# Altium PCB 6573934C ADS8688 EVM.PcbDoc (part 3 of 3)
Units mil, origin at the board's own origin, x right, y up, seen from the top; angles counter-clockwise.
Board outline 4100 x 2700 mil, 6 copper layers (L1_Analog, L2_GND, L3_AnalogPower, L4_DigPower, L5_GND, L6_Digital), stack 58.4 mil thick; 282 components, 187 nets, 719 pads, 318 vias.
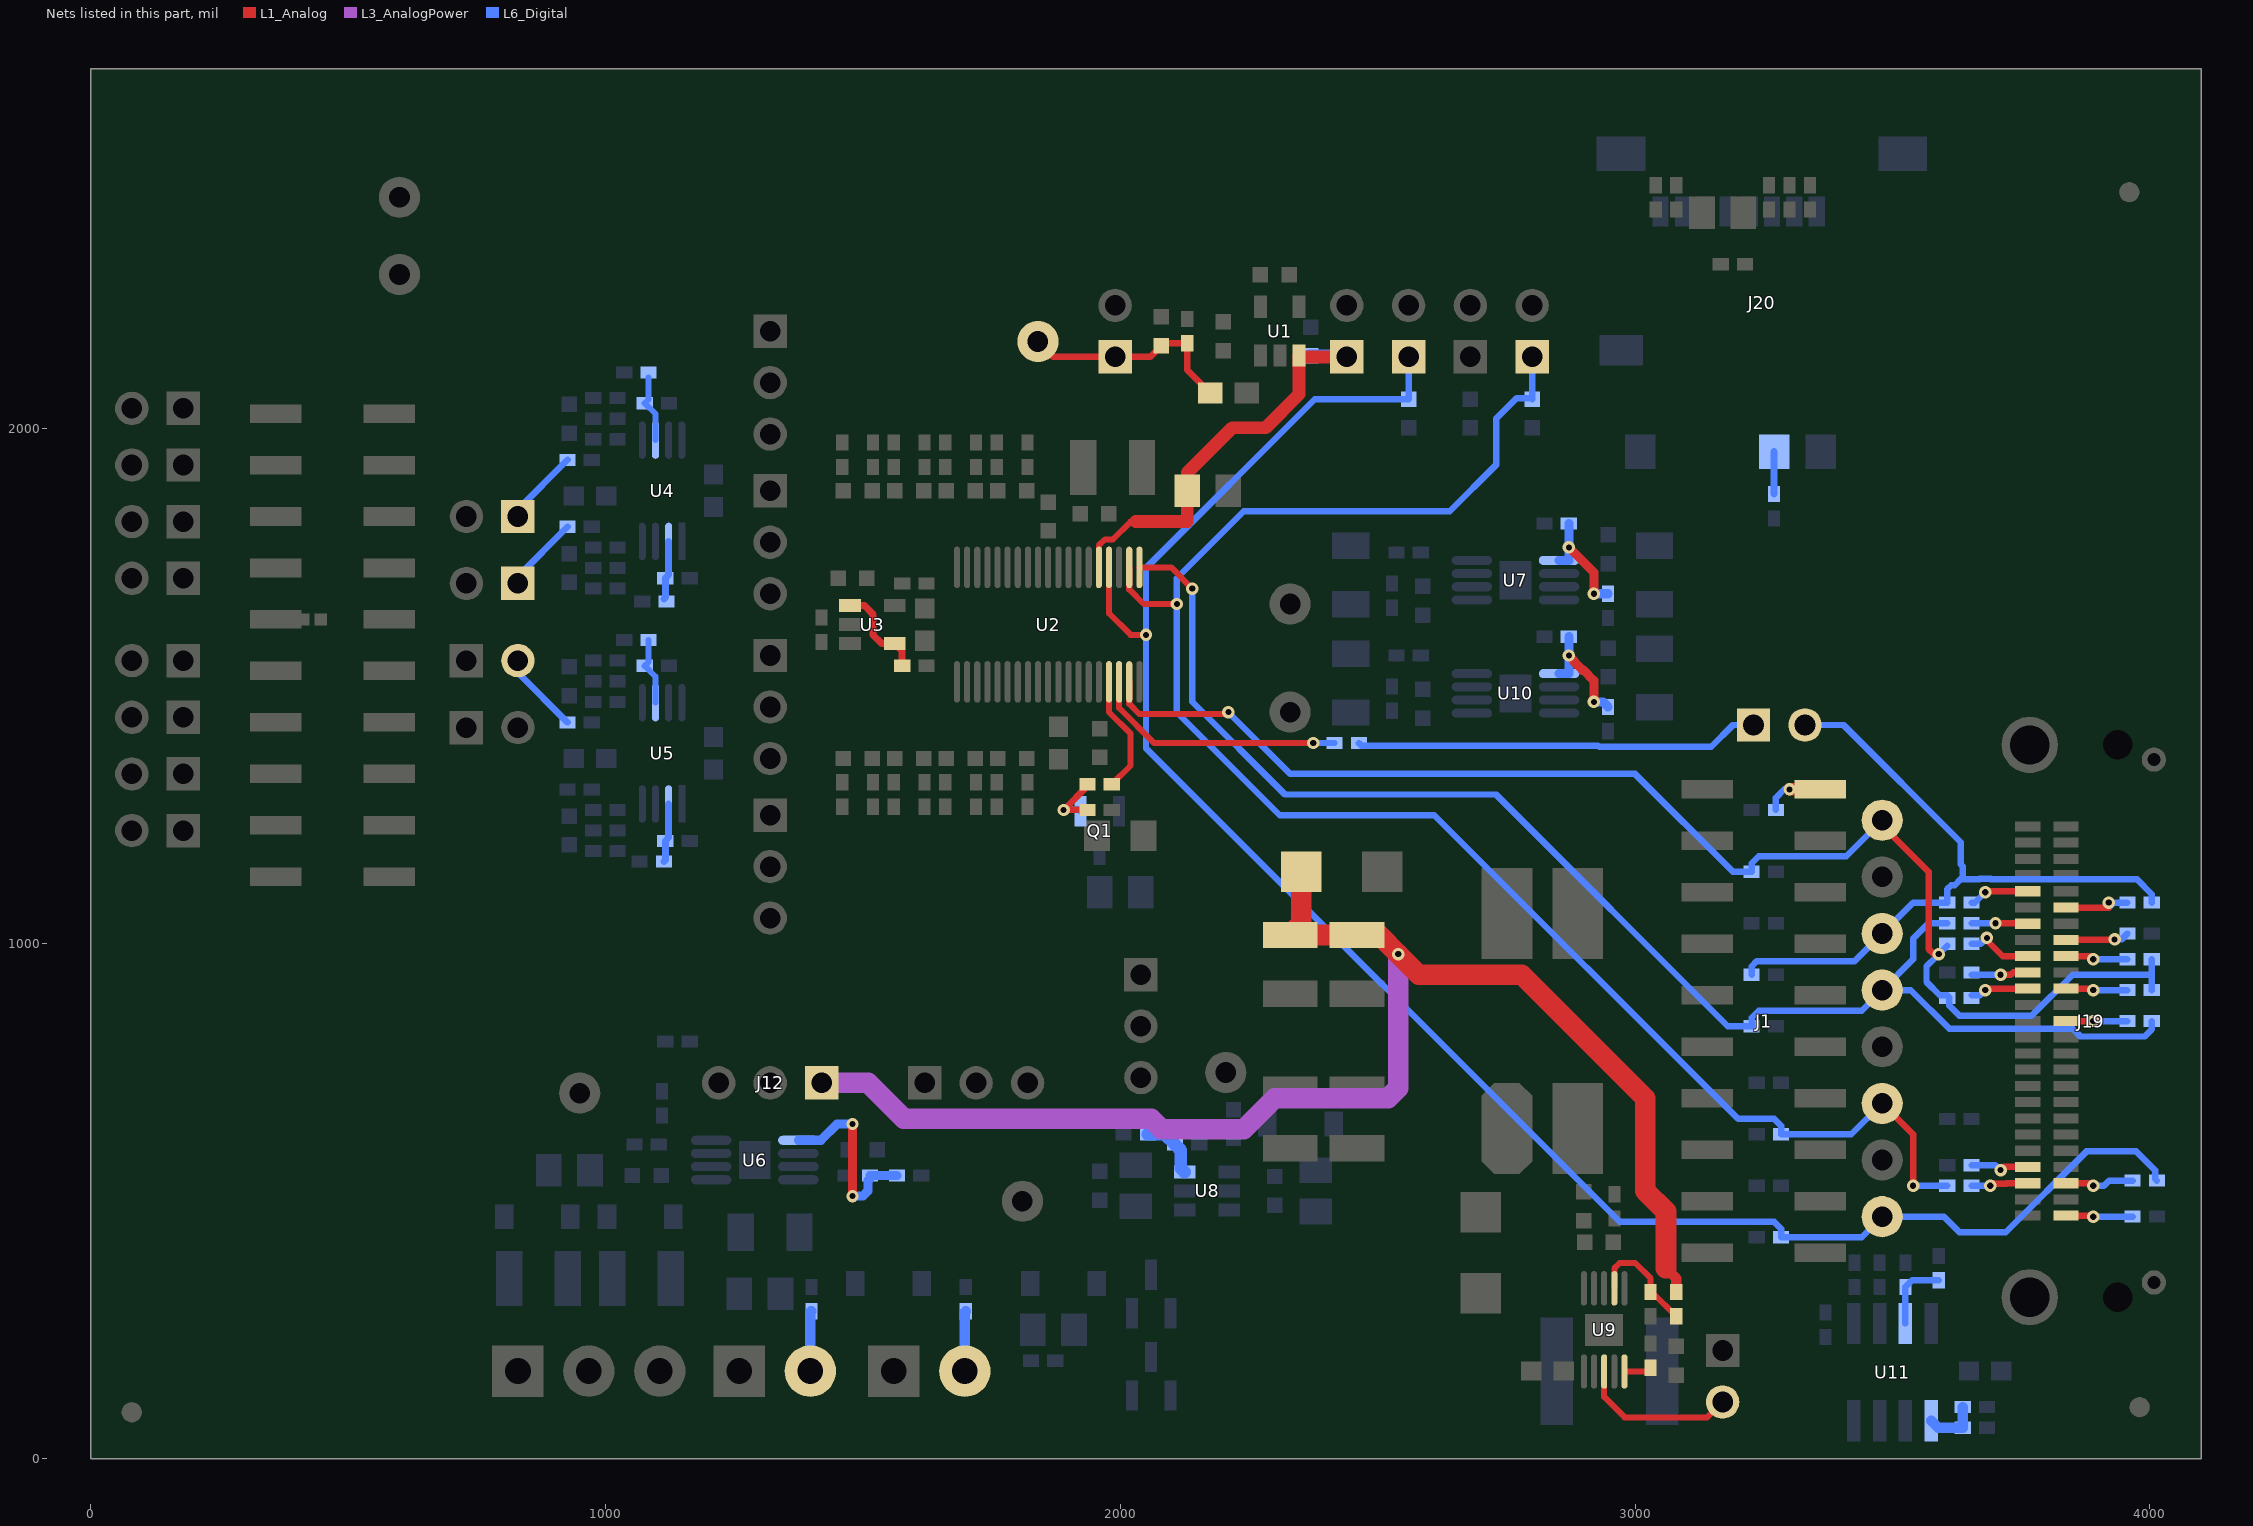
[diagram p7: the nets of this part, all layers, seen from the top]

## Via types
v1: diameter 24, hole 12, L1_Analog to L6_Digital, tented both sides, 318 vias

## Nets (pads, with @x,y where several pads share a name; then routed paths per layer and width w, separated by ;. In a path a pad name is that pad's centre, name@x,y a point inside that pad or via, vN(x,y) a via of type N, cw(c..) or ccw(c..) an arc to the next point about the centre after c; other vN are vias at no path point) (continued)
NetJ17_2: J17.2 U9.3 | length 308.3
  L1_Analog w11.81: U9.3@2940,169.29 2940,120 2980,80 3140,80 J17.2@3170,110
NetJ19_1: J19.1 R89.2 | length 130.2
  L1_Analog w12.52: J19.1@3837.01,472.05 3887.95,472.05 v1(3890,470)
  L6_Digital w12.52: v1(3890,470) R89.2@3966.38,470
NetJ19_5: J19.5 R91.2 | length 135.6
  L1_Analog w12.52: J19.5@3837.01,535.04 3884.96,535.04 v1(3890,530)
  L6_Digital w12.52: v1(3890,530) 3910.71,530 3920.71,540 R91.2@3966.38,540
NetJ19_6: J19.6 R87.1 | length 112.4
  L1_Analog w12.52: v1(3690,530) 3695.04,535.04 3698,535.04 3699.17,533.87 3720.83,533.87 3722,535.04 J19.6@3762.99,535.04
  L6_Digital w12.52: R87.1@3653.62,530 v1(3690,530)
NetJ19_8: J19.8 R86.1 | length 117.2
  L1_Analog w12.52: v1(3710,560.5) 3710,560 3716.54,566.54 J19.8@3762.99,566.54
  L6_Digital w12.52: R86.1@3653.62,570 3700,570 3710,560 v1(3710,560.5)
NetJ19_25: J19.25 R100.2 | length 119.4
  L1_Analog w12.52: J19.25@3837.01,850 v1(3890,850)
  L6_Digital w12.52: v1(3890,850) R100.2@3956.38,850
NetJ19_29: J19.29 R99.2 | length 120.6
  L1_Analog w12.52: J19.29@3837.01,912.99 3887.01,912.99 v1(3890,910)
  L6_Digital w12.52: v1(3890,910) R99.2@3956.38,910
NetJ19_30: J19.30 R107.1 | length 131.1
  L1_Analog w12.52: v1(3680,910) 3682.99,912.99 J19.30@3762.99,912.99
  L6_Digital w12.52: v1(3680,910) 3670,900 ; 3670,900 3653.62,900 3670,900
NetJ19_32: J19.32 R103.1 | length 111.2
  L1_Analog w12.52: v1(3710,940) 3730,940 3734.49,944.49 J19.32@3762.99,944.49
  L6_Digital w12.52: R103.1@3653.62,940 v1(3710,940)
NetJ19_33: J19.33 R93.2 | length 121.8
  L1_Analog w12.52: J19.33@3837.01,975.98 3884.02,975.98 v1(3890,970)
  L6_Digital w12.52: v1(3890,970) R93.2@3956.38,970
NetJ19_34: J19.34 R101.1 | length 150
  L1_Analog w12.52: v1(3683.36,1011.56) 3683.36,1006.64 3714.02,975.98 J19.34@3762.99,975.98
  L6_Digital w12.52: v1(3683.36,1011.56) 3671.81,1000 ; 3671.81,1000 R101.1@3653.62,1000 3671.81,1000
NetJ19_35: J19.35 R90.2 | length 124.6
  L1_Analog w12.52: J19.35@3837.01,1007.48 3930.4,1007.48 v1(3931.46,1008.54)
  L6_Digital w12.52: v1(3931.46,1008.54) 3944.92,1008.54 R90.2@3956.38,1020
NetJ19_38: J19.38 R88.1 | length 109.8
  L1_Analog w12.52: v1(3700,1040) 3761.97,1040 J19.38@3762.99,1038.98
  L6_Digital w12.52: R88.1@3653.62,1040 v1(3700,1040)
NetJ19_39: J19.39 R92.2 | length 143.7
  L1_Analog w12.52: J19.39@3837.01,1070.47 3919.53,1070.47 3920,1070 v1(3920,1080)
  L6_Digital w12.52: v1(3920,1080) 3920,1070 3930,1080 R92.2@3956.38,1080
NetJ19_42: J19.42 R98.1 | length 118.5
  L1_Analog w12.52: v1(3680,1100) 3681.97,1101.97 J19.42@3762.99,1101.97
  L6_Digital w12.52: R98.1@3653.62,1080 3660,1080 v1(3680,1100)
NetJ20_9: J20.9 R85.1 | length 82.2
  L6_Digital w13.78: R85.1@3270,1873.62 J20.9@3270,1955.83
NetJ21_1: J21.1 R16.2 | length 786.8
  L6_Digital w12.52: R16.2@2463.62,1390 2468.62,1385 2927.92,1385 2930.05,1382.87 3147.87,1382.87 3190,1425 J21.1@3230,1425
NetJ25_1: J25.1 R46.2 | length 149.9
  L6_Digital w12.52: J25.1@830,1830 830,1843.62 R46.2@926.38,1940
NetJ30_2: J30.2 R54.2 | length 159.9
  L6_Digital w12.52: J30.2@830,1550 830,1526.38 R54.2@926.38,1430
NetJ31_1: J31.1 R42.1 | length 149.9
  L6_Digital w12.52: J31.1@830,1700 830,1713.62 R42.1@926.38,1810
NetJ32_2: J32.2 R69.1 | length 117.2
  L6_Digital w20: J32.2@1398,170 1398,284.38 R69.1@1400,286.38
NetJ33_2: J33.2 R106.1 | length 117.2
  L6_Digital w20: J33.2@1698,170 1698,284.38 R106.1@1700,286.38
NetQ1_1: Q1.1 R17.1 R20.2 | length 149.3
  L1_Analog w12.52: R20.2@1936.38,1260 v1(1890,1260) 1936.38,1306.38 R17.1@1936.38,1310
  L6_Digital w12.52: v1(1890,1260) 1920,1260 Q1.1@1922.6,1257.4
NetR10_1: R10.1 U3.1 U3.4 | length 190
  L1_Analog w13.78: U3.1@1475,1657 1503,1657 1520,1640 1520,1600 1537,1583 U3.4@1562,1583 1576.38,1568.62 R10.1@1576.38,1540
NetR16_1: R16.1 U2.36 | length 497.5
  L1_Analog w11.81: U2.36@1997.8,1508.78 1997.8,1458.02 2065.82,1390 v1(2375,1390)
  L6_Digital w11.81: v1(2375,1390) R16.1@2416.38,1390
NetR17_2: R17.2 U2.35 | length 231.2
  L1_Analog w11.81: U2.35@1978.11,1508.78 1978.11,1451.89 1978.11,1449.87 2020,1407.98 2020,1346.38 R17.2@1983.62,1310
NetR33_1: R33.1 R36.2 U4.2 | length 115.4
  L6_Digital w13.78: R36.2@1113.62,1670 1116.38,1672.76 R33.1@1116.38,1710 1122.8,1716.42 U4.2@1122.8,1781.57
NetR39_1: R39.1 R44.2 U4.6 | length 133.2
  L6_Digital w11.81: R44.2@1083.62,2100 1083.62,2057.24 R39.1@1076.38,2050 1097.2,2029.17 U4.6@1097.2,1978.43
NetR47_1: R47.1 R48.1 U5.2 | length 115.4
  L6_Digital w13.78: R48.1@1113.62,1160 1116.38,1162.76 R47.1@1116.38,1200 1122.8,1206.42 U5.2@1122.8,1271.57
NetR49_1: R49.1 R52.1 U5.6 | length 133.2
  L6_Digital w11.81: R52.1@1083.62,1590 1083.62,1547.24 R49.1@1076.38,1540 1097.2,1519.17 U5.6@1097.2,1468.43
NetR58_1: R58.1 R62.1 U6.5 | length 376.8
  L1_Analog w17.72: v1(1480,510) v1(1480,650)
  L6_Digital w17.72: U6.5@1374.65,618.39 1418.39,618.39 1450,650 v1(1480,650) ; v1(1480,510) 1500,510 1510,520 1510,540 1513.62,543.62 R58.1@1513.62,550 R62.1@1566.38,550
NetR60_1: R60.1 R64.2 U7.5 | length 228.5
  L1_Analog w17.72: v1(2871.34,1770) 2920,1721.34 v1(2920,1680)
  L6_Digital w17.72: U7.5@2852.36,1744.76 2871.34,1744.76 v1(2871.34,1770) R64.2@2871.34,1816.38 ; v1(2920,1680) R60.1@2947.72,1680
NetR63_2: R63.2 R65.1 U8.3 | length 121.8
  L6_Digital w25: R65.1@2053.62,630 2086.38,630 R63.2@2106.38,610 2117.5,598.88 2117.5,564.5 U8.3@2125,557
NetR66_2: R66.2 R67.1 U9.7 | length 221.9
  L1_Analog w11.81: U9.7@2959.69,330.71 2959.68,369.68 2970,380 3000,380 3030,350 R66.2@3030,323.62 3032.75,323.62 R67.1@3080,276.38
NetR68_2: R68.2 U9.5 | length 53.6
  L1_Analog w11.81: U9.5@2979.37,169.29 3022.91,169.29 R68.2@3030,176.38
NetR72_1: R72.1 R75.2 U10.5 | length 233.8
  L1_Analog w17.72: v1(2871.34,1560) 2881.27,1550.07 2881.27,1548.1 2898.1,1531.27 2900.07,1531.27 2920,1511.34 v1(2920,1470)
  L6_Digital w17.72: U10.5@2852.36,1524.76 2871.34,1524.76 v1(2871.34,1560) R75.2@2871.34,1596.38 ; v1(2920,1470) 2937.72,1470 R72.1@2947.72,1460
NetR96_2: R96.2 R104.1 U11.7 | length 181.3
  L6_Digital w12.52: U11.7@3525,262.5 R96.2@3525,333.38 3538,346.38 3550,346.38 ; 3550,346.38 R104.1@3590,346.38 3550,346.38
NetR97_1: R97.1 R102.2 U11.1 | length 107
  L6_Digital w20: U11.1@3575,73.5 3588.5,60 R97.1@3636.38,60 R102.2@3636.38,100
P18V: C32.1 C35.1 D2.1 J12.1 R67.2 | length 2804.7
  L1_Analog w20: 3060,370 3080,350 R67.2@3080,323.62
  L1_Analog w40: D2.1@2351.26,1140 2351.26,1038.35 C35.1@2330,1017.09 C32.1@2460,1017.09 2502.91,1017.09 v1(2540,980) 2580,940 2780,940 3020,700 3020,520 3060,480 3060,370
  L3_AnalogPower w40: J12.1@1420,730 1510,730 1580,660 2060,660 2080,640 2240,640 2300,700 2520,700 2540,720 v1(2540,980)
R\E\F\S\E\L\: J2.1 R9.1 R18.2 R91.1 TP9.1 U2.4 | length 3750.2
  L1_Analog w11.81: U2.4@1978.11,1731.22 1978.11,1641.89 2020,1600 v1(2050,1600)
  L6_Digital w12.52: J2.1@2560,2140 R18.2@2560,2058 2378,2058 2050,1730 v1(2050,1600) 2050,1380 2970,460 3270,460 3283.62,446.38 R9.1@3283.62,430 3440,430 TP9.1@3480,470 3600,470 3630,440 3720,440 3876.64,596.64 3973.36,596.64 4010,560 4010,543.42 4013.42,540 R91.1@4013.62,540
R\S\T\/P\D\: J3.1 R3.1 R13.2 R87.2 TP2.1 U2.2 | length 3372.8
  L1_Analog w11.81: U2.2@2017.48,1731.22 2017.48,1688.62 2046.1,1660 v1(2110,1660)
  L1_Analog w12.52: TP2.1@3480,690 3540,630 v1(3540,530)
  L6_Digital w12.52: J3.1@2800,2140 R13.2@2800,2058 2798,2060 2770,2060 2730,2020 2730,1930 2640,1840 2240,1840 2110,1710 v1(2110,1660) 2110,1450 2310,1250 2610,1250 3200,660 3270,660 3283.62,646.38 R3.1@3283.62,630 3420,630 TP2.1@3480,690 ; v1(3540,530) R87.2@3606.38,530
REFIN: C3.1 C7.1 J5.1 U1.3 U2.5 | length 848.8
  L1_Analog w11.81: U2.5@1958.43,1731.22 1958.43,1773.82 1969.96,1785.35 1985.35,1785.35 2020,1820 2030,1820
  L1_Analog w25: 2030,1820 2130,1820 C7.1@2130,1880 2130,1915 2217.5,2002.5 2282.5,2002.5 2347.4,2067.4 U1.3@2347.4,2142.76 2350.16,2140 J5.1@2440,2140
  L6_Digital w25: C3.1@2370,2142 2438,2142 J5.1@2440,2140
REFOUT: C6.1 J6.1 R1.2 R19.1 TP10.1 | length 428.2
  L1_Analog w12.52: TP10.1@1840,2170 1870,2140 J6.1@1990,2140 2058,2140 C6.1@2080,2162 2084.38,2166.38 R1.2@2130,2166.38 2130,2114.57 R19.1@2174.57,2070
SCLK: R6.1 R93.1 R99.1 R101.2 R107.2 TP6.1 U2.37 | length 2655.5
  L1_Analog w11.81: U2.37@2017.48,1508.78 2017.48,1466.18 2037.4,1446.26 2206.26,1446.26 v1(2210,1450)
  L1_Analog w12.52: TP6.1@3480,1240 3480,1230 3570,1140 3570,990 3580,980 v1(3590,980)
  L6_Digital w12.52: v1(2210,1450) 2330,1330 3000,1330 3190,1140 R6.1@3226.38,1140 3226.38,1156.38 3240,1170 3410,1170 TP6.1@3480,1240 ; R107.2@3606.38,900 3592,900 3566,926 3566,956.17 3584.78,974.94 3584.95,974.94 R101.2@3606.38,996.37 ; R107.2@3610,896.38 3610,880 3630,860 3770,860 3850,940 4003.62,940 ; R99.1@4003.62,910 4003.62,940 ; R93.1@4003.62,970 4003.62,940
SDI: R5.1 R88.2 R100.1 TP5.1 U2.1 | length 2766
  L1_Analog w11.81: U2.1@2037.17,1731.22 2098.78,1731.22 v1(2140,1690)
  L6_Digital w12.52: v1(2140,1690) 2140,1470 2320,1290 2730,1290 3180,840 R5.1@3226.38,840 3226.38,856.38 3240,870 3440,870 TP5.1@3480,910 ; R88.2@3606.38,1040 3570,1040 3540,1010 3540,970 TP5.1@3480,910 ; R100.1@4003.62,850 4003.62,833.62 3990,820 3865,820 3850,835 3610.55,835 3535.55,910 TP5.1@3480,910
SDO: J21.2 R4.1 R92.1 R98.2 TP4.1 | length 1379.8
  L6_Digital w12.52: R4.1@3226.38,940 3226.38,956.38 3235.95,965.95 3395,965.95 3425.24,965.94 3425.59,965.59 TP4.1@3480,1020 3540,1080 R98.2@3606.38,1080 3606.38,1106.38 3613.87,1113.87 3620.83,1113.87 3632.74,1125.78 ; J21.2@3330,1425 3405,1425 3632.74,1197.26 3632.74,1154.22 3636.13,1150.82 3636.13,1129.18 3632.74,1125.78 ; R92.1@4003.62,1080 4003.62,1096.38 3974.22,1125.78 3691.18,1125.78 3690.83,1126.13 3669.17,1126.13 3668.82,1125.78 3632.74,1125.78
VBUS_LP: J1.2 R61.2 | length 116.8
  L1_Analog w24: v1(3300,1300) J1.2@3360,1300
  L6_Digital w12.52: R61.2@3273.62,1260 3273.62,1283.62 3290,1300 v1(3300,1300)
pads on no net: D9.1 FID1.1 FID2.1 FID3.1 FID4.1 FID5.1 FID6.1 H1.0 H2.0 H3.0 H4.0 J19.M1 J19.M2 J19.MH1 J19.MH2 J19.MH3 J19.MH4 SH-J2.0 SH-J3.0 SH-J4.0 SH-J5.0 SH-J6.0 SH-J8.0 SH-J9.0 SH-J10.0 SH-J11.0 SH-J12.0 SH-J13.0 SH-J14.0 SH-J15.0 SH-J16.0 SH-J17.0 SH-J21.0 SH-J22.0 SH-J23.0 SH-J24.0 SH-J25.0 SH-J26.0 SH-J27.0 SH-J28.0 SH-J29.0 SH-J30.0 SH-J31.0 U6.3 U6.7 U7.3 U7.7 U9.6 U10.3 U10.7

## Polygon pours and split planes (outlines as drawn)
GND on L6_Digital "L6_Digital-No Net" (solid, remove dead copper, pour order 34): 0,0 0,2700 4105,2700 4105,0
DVDD on L4_DigPower "L4_DigPower-No Net" (solid, remove dead copper, pour order 23): 0,0 0,2700 4105,2700 4105,0
NetD2_2 on L1_Analog "Top Layer-No Net 4" (solid, pour order 24): 2320,1190 2470,1190 2470,850 2320,850 2320,1180
P18V on L1_Analog "Top Layer-No Net 3" (solid, pour order 22): 2000,960 2000,1190 2320,1190 2320,960 2000,960
N18V on L1_Analog "Top Layer-No Net 1" (solid, pour order 18): 2000,660 2320,660 2320,400 2500,400 2500,290 2750,290 2750,200 2580,200 2580,190 2000,190 2000,660
GND on L1_Analog "Top Layer-No Net" (solid, pour order 21): 2320,660 1960,660 1960,870 1960,960 2320,960 2320,850 2470,850 2470,1060 2640,1060 2770,1060 2770,540 2590,540 2470,540 2470,730 2320,730 2320,660
NetC45_1 on L1_Analog "L1_Analog-No Net 1" (solid, remove dead copper, pour order 19): 2500,290 2499.87,290.13 2499.87,399.87 2320.13,399.87 2320,400 2320,690 2520,690 2520,540 2700,540 2700,730 2820,730 2830,720 2830,540 2830,470 2830,460 2910,380 2910,290 2500,290
GND on L1_Analog "L1_Analog-No Net" (solid, remove dead copper, pour order 33): 0,0 0,2700 4105,2700 4105,0
NetD10_2 on L3_AnalogPower "L3_AnalogPower-No Net 1" (solid, remove dead copper, pour order 25): 3010,1340 3010,230 3330,230 3340,240 3300,280 3300,1340
3V3_LP on L3_AnalogPower "L3_AnalogPower-No Net 2" (solid, remove dead copper, pour order 26): 3010,1350 2850,1350 2760,1260 2770,1250 2770,420 2770,382.59 2910.35,242.24 2918.38,250.27 3010,250.27
P18V on L3_AnalogPower "L3_AnalogPower-No Net 3" (solid, remove dead copper, pour order 27): 1960,600 1631.22,600 1630.53,600.68 1640,610.15 1640,980 1640,983.85 1730,1073.85 1736.15,1080 1970,1080
HVDD on L3_AnalogPower "L3_AnalogPower-No Net 4" (solid, remove dead copper, pour order 28): 1970,1090 1970,870 2190,1090 1970,1090
HVSS on L3_AnalogPower "L3_AnalogPower-No Net 5" (solid, remove dead copper, pour order 29): 2030,1450 2640,1450 2350,1160 2340,1160 1760,1160 1750,1150 1740,1150 1670,1150 1660,1140 1560,1040 1270,1040 1250,1020 1240,1010 1200,1010 1070,880 680,880 680,1070 690,1060 1130,1060 1173.24,1060 1298.75,1185.51 1301.35,1188.11 1477.66,1188.11 1493.32,1188.11 1569.43,1264.22 1583.65,1250 1950,1250 1950,1450 1947.75,1452.25 1947.75,1481.28 1951.28,1481.28 1990,1520 2080,1520 2120,1480 2120,1450
P18V on L3_AnalogPower "L3_AnalogPower-No Net 6" (solid, remove dead copper, pour order 30): 1560,950 1350,950 1350,1000 1250,1000 1190,940 1130,880 731.89,880 731.89,671.89 730,670 1070,670 1110,710 1210,710 1210,710.24 1331.65,831.89 1333.53,830 1560,830
HVSS on L3_AnalogPower "L3_AnalogPower-No Net 7" (solid, remove dead copper, pour order 31): 2710,1540 2830,1540 2830,2580 2770,2640 2770,2650 2710,2650 2710,2610 2710,2580.24 2721.89,2568.35 2731.75,2558.49 2731.75,1755.67 2731.75,1725.12 2678.88,1672.25 2710,1641.12 2710,1540
HVDD on L3_AnalogPower "L3_AnalogPower-No Net 8" (solid, remove dead copper, pour order 32): 2458.35,2531.89 2460,2533.53 2460,2680 1230,2680 1230,2320 1340,2320 1430,2410 1460,2410 1510,2410 1520,2420 1620,2520 2460,2520 2458.35,2521.65 2458.35,2531.89
AVDD on L3_AnalogPower "L3_AnalogPower-No Net" (solid, remove dead copper, pour order 20): 0,0 0,2700 4100,2700 4100,0
GND on L2_GND (split plane): 4079.9,20.1 20.1,20.1 20.1,2679.9 4079.9,2679.9
GND on L5_GND (split plane): 4079.9,20.1 20.1,20.1 20.1,2679.9 4079.9,2679.9

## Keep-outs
Keep-Out Layer:
  lines w10: -5,0 ccw(c0,0) 0,-5 ; -5,0 ccw(c0,0) 0,-5 ; -5,0 -5,2700 ; -5,2700 cw(c0,2700) 0,2705 ; -5,2700 cw(c0,2700) 0,2705 ; 0,-5 4100,-5 ; 0,2705 4100,2705 ; 4100,-5 ccw(c4100,0) 4105,0 ; 4100,-5 ccw(c4100,0) 4105,0 ; 4100,2705 cw(c4100,2700) 4105,2700 ; 4100,2705 cw(c4100,2700) 4105,2700 ; 4105,0 4105,2700
  text ".Layer_Name" at 527,-858.49 h60

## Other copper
L1_Analog:
  text ".Layer_Name" at 527,-858.49 h60
L6_Digital:
  rectangle net NetD10_1: 3565,700 3647.57,780
  region net NetC46_1: 2050,170 2210,170 2210,265 2120,265 2120,240 2050,240
  text ".Layer_Name" at 527,-858.49 h60
L2_GND (plane layer: these items are gaps in the copper):
  lines w10: 10,1690 10,10 3190,10

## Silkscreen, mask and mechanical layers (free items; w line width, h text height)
Top Overlay:
  region: 3805,1880 3895,1880 3895,1790 3805,1790
  region: 3805,1780 3895,1780 3895,1690 3805,1690
  region: 3805,1680 3895,1680 3895,1590 3805,1590
  region: 2955,1680 3045,1680 3045,1590 2955,1590
  region: 2955,1780 3045,1780 3045,1690 2955,1690
  region: 2955,1880 3045,1880 3045,1790 2955,1790
  lines w10: 2940,1580 3910,1580 3910,1990 2940,1990 2940,1580
  text "ADS868x/ADS867x/ADS866x EVM" at 760,2530 h150
  text "-" at 350,2110 h40
  text "+" at 570,2110 h40
  text "1" at 270,2080 h30
  text "TI" at 2930,2080 h230
  text "A6" at 250,2060 h40 r270
  text "A7" at 250,1960 h40 r270
  text "Installed Device:" at 2960,1920 h75
  text "A0" at 250,1860 h40 r270
  text "ADS8688" at 3060,1810 h75
  text "ADS8684" at 3500,1810 h75
  text "A1" at 250,1750 h40 r270
  text "ADS8678" at 3060,1710 h75
  text "ADS8674" at 3500,1710 h75
  text "AUX" at 260,1670 h30 r270
  text "ADS8668" at 3060,1610 h75
  text "ADS8664" at 3500,1610 h75
  text "A2" at 250,1560 h40 r270
  text "A3" at 250,1460 h40 r270
  text "A4" at 250,1360 h40 r270
  text "A5" at 250,1260 h40 r270
  text "1" at 3033.43,1253 h30
  text ".Layer_Name" at 527,-858.49 h60
Bottom Overlay:
  text ".PRJ_Rev" at 1660,2590 h60
  text ".PRJ_BasePN" at 2080,2590 h60
  text ".Layer_Name" at 527,-858.49 h60
Top Paste:
  text ".Layer_Name" at 527,-858.49 h60
Bottom Paste:
  text ".Layer_Name" at 527,-858.49 h60
Top Solder:
  text ".Layer_Name" at 527,-858.49 h60
  text ".Layer_Name" at 527,-858.49 h60
Bottom Solder:
  text ".Layer_Name" at 527,-858.49 h60
Drill Guide:
  text ".Layer_Name" at 527,-858.49 h60
M1 Board Outline:
  the board outline again, w10
M2 Board Dimensions:
  rectangle: -0.5,-285.5 124.5,-160.5
  rectangle: 124.5,-410.5 499.5,-285.5
  lines w7: -0.5,-285.5 999.5,-285.5 ; 124.5,-410.5 124.5,-160.5 ; 249.5,-410.5 249.5,-160.5 ; 499.5,-410.5 499.5,-160.5 ; 749.5,-410.5 749.5,-160.5 ; -0.5,-410.5 999.5,-410.5 999.5,-160.5 -0.5,-160.5 -0.5,-410.5
  lines w10: -0.5,-475.5 -0.5,-455.5 ; 59.5,-485.5 -0.5,-465.5 ; 59.5,-445.5 -0.5,-465.5 ; 223.58,-465.5 -0.5,-465.5 ; 775.42,-465.5 999.5,-465.5 ; 939.5,-485.5 999.5,-465.5 ; 939.5,-445.5 999.5,-465.5 ; 999.5,-475.5 999.5,-455.5
  text "1000 (mil)" at 233.58,-501.49 h60
  text ".Layer_Name" at 577,-858.49 h60
M3 3D STEP Top:
  text ".Layer_Name" at 577,-858.49 h60
M4 3D STEP Bottom:
  text ".Layer_Name" at 577,-858.49 h60
M5 Assembly Top:
  lines w10: -496.51,-1129 4403.49,-1129 ; -496.51,-929 4403.49,-929 ; 2203.49,-929 2203.49,-729 ; -496.51,-1329 4403.49,-1329 4403.49,-729 -496.51,-729 -496.51,-1329
  text "ASSEMBLY, TOP," at 11103.49,-279 h150
  text "COMPONENTS MARKED 'DNI' SHOULD NOT BE POPULATED, AND MAY NOT BE IN BILL OF MATERIALS" at 1353.49,-379 h60
  text "ASSEMBLY VARIANT:" at 1353,-484 h60
  text ".VariantName" at 2389,-484 h60
  text "PCB VIEWED FROM TOP SIDE" at -246.51,-679 h60
  text ".Layer_Name" at 577,-858.49 h60
  text "LAYER NAME =" at -246.51,-879 h60
  text "ARTWORK #    =" at 2253.49,-879 h60
  text ".PRJ_BasePN" at 3253.49,-879 h60
  text ".PCB_Rev" at 3753.49,-879 h60
  text "PLOT NAME =" at -246.51,-1079 h60
  text ".plot_File_Name" at 553.49,-1079 h60
  text "1" at 13688,-1240.65 h80
  text "GENERATED    :" at -246.51,-1279 h60
  text ".Print_Date" at 622.99,-1279 h60
  text ".Print_Time" at 1303.49,-1279 h60
  text "2" at 13981,-1295.65 h80
M6 Assembly Bottom:
  lines w10: -496.51,-1129 4403.49,-1129 ; -496.51,-929 4403.49,-929 ; 2203.49,-929 2203.49,-729 ; -496.51,-1329 -496.51,-729 4403.49,-729 4403.49,-1329 -496.51,-1329
  text "ASSEMBLY, BOTTOM," at 11103.49,-279 h150
  text "COMPONENTS MARKED 'DNI' SHOULD NOT BE POPULATED, AND MAY NOT BE IN BILL OF MATERIALS" at 1353.49,-379 h60
  text "ASSEMBLY VARIANT:" at 1353.49,-479 h60
  text ".VariantName" at 2389,-484 h60
  text "PCB VIEWED FROM TOP SIDE" at -246.51,-679 h60
  text "LAYER NAME =" at -246.51,-879 h60
  text "ARTWORK #    =" at 2253.49,-879 h60
  text ".PRJ_BasePN" at 3253.49,-879 h60
  text ".PCB_Rev" at 3753.49,-879 h60
  text "PLOT NAME =" at -246.51,-1079 h60
  text ".plot_File_Name" at 553.49,-1079 h60
  text "2" at 13688,-1240.65 h80
  text "GENERATED    :" at -246.51,-1279 h60
  text ".Print_Date" at 622.99,-1279 h60
  text ".Print_Time" at 1303.49,-1279 h60
  text "2" at 13981,-1295.65 h80
M9 Title Sheet:
  drawing of 228 lines, arcs and shapes, not listed
  text "1" at 534.83,7841 h70
  text "2" at 3030.49,7841 h70
  text "3" at 5519.84,7841 h70
  text "4" at 8026.5,7841 h70
  text "5" at 10525.49,7841 h70
  text "6" at 13030.49,7841 h70
  text "SYM" at 11283.72,7663.3 h90
  text "REVISIONS" at 12450,7650 h90
  text "A" at 11376.36,7379.35 h100
  text "06/07/2013" at 11681,7379.35 h100
  text "," at 12661,7379.35 h100
  text "B McKay" at 12931,7379.35 h100
  text "B" at 11376.36,7129.35 h100
  text "12/09/2013" at 11681,7129.35 h100
  text "," at 12661,7129.35 h100
  text "B McKay" at 12931,7129.35 h100
  text "C" at 11376.36,6879.35 h100
  text "03/13/2014" at 11681,6879.35 h100
  text "," at 12661,6879.35 h100
  text "B McKay" at 12931,6879.35 h100
  text "A" at -621.51,6698 h70
  text "A" at 14178.49,6698 h70
  text "B" at -621.51,4318 h70
  text "B" at 14178.49,4318 h70
  text "PROCESSES:" at 11044.01,2316.57 h76
  text "MATERIAL:" at 9485.96,2309.98 h76
  text "C" at -621.51,1943 h70
  text "C" at 14178.49,1943 h70
  text "NEXT ASSEMBLY" at 12888.64,1748 h76
  text "SURFACE" at 13508.83,1570.43 h59
  text "TOLERANCES UNLESS OTHERWISE SPECIFIED" at 9992.61,1514.88 h85
  text "ROUGHNESS" at 13452.84,1480.01 h59
  text "LINEAR" at 10271.94,1268.88 h80
  text "MISCELLANEOUS" at 11933.99,1268.88 h80
  text "MILLIMETERS" at 9700.02,1148.88 h50
  text "INCHES" at 10792.32,1148.88 h50
  text "o" at 12160.51,1114.27 h20
  text "ANGLES +/- 1" at 11560.29,1073.88 h50
  text ".XX  +/- .25" at 9581.29,1023.88 h50
  text ".XXX +/- .010" at 10646.52,1023.88 h50
  text "o" at 12735.51,989.27 h20
  text "o" at 13060.51,989.27 h20
  text "THIRD ANGLE" at 13407,963.81 h59
  text ".X   +/- .50" at 9581.31,948.88 h50
  text ".XX  +/- .020" at 10581.82,948.88 h50
  text "AXIS OF TAPPED HOLES 90  +/- 1" at 11560.29,948.88 h50
  text "PROJECTION" at 13439.75,866.11 h59
  text "REMOVE ALL BURRS & SHARP EDGES" at 11560.29,823.88 h50
  text "HOLES" at 10285.6,797.29 h80
  text "MILLIMETERS" at 9704.37,698.88 h50
  text "INCHES" at 10796.67,698.88 h50
  text ".XXX +/- .076" at 9581.28,573.88 h50
  text ".XXX +/- .003" at 10581.28,573.88 h50
  text ".XX  +/- .127" at 9581.29,498.88 h50
  text ".XX  +/- .005" at 10581.28,498.88 h50
  text "DATE" at 10486.45,291.8 h59
  text "CODE IDENTITY" at 13402.46,288.55 h51
  text "DRAFTSMAN:" at 9443.49,283.36 h59
  text "NUMBER" at 13550.1,215.25 h51
  text ".PRJ_Draftsman" at 9456,139.39 h60
  text ".PRJ_ReleaseDate" at 10368,136.54 h60
  text "SEMICONDUCTOR OPERATIONS" at 12100,120.04 h50
  text "01295" at 13465.68,85.84 h106
  text "TI" at 11050,50.04 h300
  text "DESIGNER:" at 9443.49,-9.86 h59
  text "DATE" at 10476.45,-11.42 h59
  text "TITLE:" at 11044.06,-89.16 h59
  text ".PRJ_Designer" at 9456,-135.61 h60
  text ".PRJ_ReleaseDate" at 10368,-143.46 h60
  text "CHECKER:" at 9443.49,-307.34 h59
  text "DATE" at 10471.45,-313.89 h59
  text "D" at -621.51,-427 h70
  text "D" at 14178.49,-427 h70
  text ".PRJ_Checker" at 9446,-430.61 h60
  text ".PRJ_ReleaseDate" at 10368,-433.46 h60
  text ".PRJ_Title1" at 11055.99,-540.61 h150
  text "DATE" at 10471.45,-567.36 h59
  text "ENGINEER:" at 9443.49,-570.81 h59
  text ".PRJ_Engr" at 9436,-700.61 h60
  text ".PRJ_ReleaseDate" at 10368,-703.46 h60
  text ".PRJ_Title2" at 11065.99,-765.61 h150
  text "Texas Instruments (TI) and/or its licensors do not warrant the accuracy or completeness of this specification" at 4456.49,-801.8 h45
  text "APPROVED:" at 9443.49,-834.28 h59
  text "DATE" at 10476.45,-835.84 h59
  text "or any information contained therein. TI and/or its licensors do not warrant that this design will meet" at 4411.51,-914.46 h45
  text ".PRJ_Release" at 9426,-970.61 h60
  text ".PRJ_ReleaseDate" at 10368,-973.46 h60
  text ".PRJ_Title3" at 11065.99,-990.61 h150
  text "the specifications, will be suitable for your application or fit for any particular purpose, or will operate in" at 4411.51,-1027.13 h45
  text "RELEASED:" at 9443.49,-1114.75 h59
  text "SHEET" at 13684.86,-1132.5 h51
  text "SCALE" at 11065.53,-1133.59 h51
  text "DATE" at 10476.45,-1136.31 h59
  text "an implementation. TI and/or its licensors do not warrant that the design is production worthy. You should" at 4411.51,-1139.79 h45
  text ".PRJ_Rev" at 13391,-1195.61 h100
  text "B" at 11472.79,-1218.96 h125
  text "B McKay" at 9446,-1250.61 h60
  text "completely validate and test your design implementation to confirm the system functionality for your application." at 4456.49,-1252.46 h45
  text ".PRJ_ReleaseDate" at 10368,-1253.46 h60
  text ".PRJ_BasePN" at 11919.5,-1265.61 h150
  text "N" at 11147.45,-1278.96 h100
  text "REV" at 13392.02,-1291.88 h51
  text "SIZE" at 11430.21,-1294.17 h51
  text "1" at 534.83,-1459 h70
  text "2" at 3030.49,-1459 h70
  text "3" at 5519.84,-1459 h70
  text "4" at 8026.5,-1459 h70
  text "5" at 10525.49,-1459 h70
  text "6" at 13030.49,-1459 h70
M10 Fab Notes:
  drawing of 203 lines, arcs and shapes, not listed
  text "NOTES:" at 11262,6032 h100
  text "1. MAXIMUM ALLOWABLE LINE REDUCTION TO BE" at 11292,5892 h60
  text "20% OR .002 WHICHEVER IS GREATER" at 11551.44,5766.91 h60
  text "DESIGN INFORMATION" at 7001.02,5750 h60
  text "HOLES TO BE .002 INCH" at 11575.17,5641.91 h60
  text "(REFER ALSO ARRAY/PANEL PROFILING INFORMATION)" at 6639.46,5588.29 h60
  text "BOARD SIZE" at 5953.46,5584 h60
  text "3800MIL" at 6415.78,5456.18 h60
  text "X" at 6921.46,5456.18 h60
  text "2700MIL" at 7152.78,5456.18 h60
  text "2. 0.318mm TRACES ON TOP AND BOTTOM" at 11292,5432 h60
  text "LAYERS ARE TO BE 50 OHMS." at 11552,5292 h60
  text "Number of Layers :" at 6356.46,5259 h60
  text "6" at 7451.27,5249 h60
  text "MIN. TRACK WIDTH:" at 6356.46,5120 h60
  text "11.8" at 7380,5120 h60
  text "MIL" at 7607.46,5120 h60
  text "8" at 7450,4990 h60
  text "MIN. CLEARANCE:" at 6356.46,4988 h60
  text "MIL" at 7607.46,4988 h60
  text "MIN. VIA PAD SIZE:" at 6356.46,4856 h60
  text "24" at 7422.71,4856 h60
  text "MIL" at 7607.46,4856 h60
  text "0.05mm (2MIL)" at 7051.46,4714.29 h60
  text "MINIMUM ANNULAR RING" at 6027.23,4710 h60
  text "EXTERNAL" at 7759.46,4710 h60
  text "PER" at 6227.23,4592 h60
  text "IPC-D-275 CLASS 2 LEVEL C" at 6447.23,4592 h60
  text "MIL, HOLES" at 7935.46,4479.71 h60
  text "+/-" at 7543,4479 h60
  text "+/-" at 8397,4479 h60
  text "REGISTRATION TOLERANCES:" at 6027.23,4474 h60
  text "METAL" at 7227,4474 h60
  text "5" at 7803.2,4474 h60
  text "3" at 8636.2,4474 h60
  text "MIL" at 8752.46,4474 h60
  text "MATERIAL:" at 5952.46,4264.54 h60
  text "FR-4 High Tg" at 6938.9,4124.21 h60
  text "FR-4" at 6413.46,4115.64 h60
  text "OTHER" at 7861.46,4115.64 h60
  text "X" at 6220,4110 h60
  text "62 MIL (1.6mm) +/-10%" at 6693.56,3952.92 h60
  text "THICKNESS:" at 6027.23,3948.64 h60
  text "X" at 6565.4,3948.64 h60
  text "OTHER" at 7978.46,3948.64 h60
  text "TOLERANCE:" at 6027.23,3790.64 h60
  text "X" at 6866.53,3790.64 h60
  text "ANSI IPC-6012 TYPE 3 CLASS 2" at 7053.48,3790.64 h60
  text "OTHER +/-" at 7053.46,3634.64 h60
  text "BOW & TWIST:" at 6027.23,3477.64 h60
  text "X" at 6866.53,3477.64 h60
  text "ANSI IPC-6012 TYPE 3 CLASS 2" at 7053.48,3477.64 h60
  text "OTHER +/-" at 7053.46,3319.13 h60
  text "COPPER THICKNESS (FINISHED):" at 5952.46,3183.64 h60
  text "1.4MIL (1oz)" at 6832.46,3030.92 h60
  text "2MIL (1.4oz)" at 7599.46,3030.92 h60
  text "2.8MIL (2oz)" at 8326.46,3030.92 h60
  text "OUTER:" at 6309.46,3026.64 h60
  text "X" at 6704,3026 h60
  text "1.4MIL (1oz)" at 7182.46,2873.92 h60
  text "2.8MIL (2oz)" at 8026.46,2873.92 h60
  text "INNER SIGNAL:" at 6309.46,2869.64 h60
  text "X" at 7055.42,2869.64 h60
  text "DRILLING:" at 5952.46,2730.64 h60
  text "REFERENCE:" at 6027.23,2613.64 h60
  text "X" at 6675.46,2613.64 h60
  text "AS SHOWN" at 6862.46,2613.64 h60
  text "X" at 7576.46,2613.64 h60
  text "NC_DRILL FILES" at 7713.46,2613.64 h60
  text "PTH MIN COPPER THICKNESS:" at 6027.23,2455.64 h60
  text "X" at 7377.46,2455.64 h60
  text "1MIL" at 7514.46,2455.64 h60
  text "OTHER" at 8011.46,2455.64 h60
  text "BOARD FINISH:" at 5952.46,2296.64 h60
  text "SILKSCREEN:" at 6107.68,2178.64 h60
  text "X" at 7056.46,2178.64 h60
  text "TOP" at 7182.46,2178.64 h60
  text "X" at 7566.46,2178.64 h60
  text "BOTTOM" at 7693.46,2178.64 h60
  text "SILKSCREEN COLOR:" at 6107.68,2011.64 h60
  text "X" at 7055.42,2011.64 h60
  text "WHITE" at 7182.46,2011.64 h60
  text "OTHER" at 7693.46,2011.64 h60
  text "SOLDER RESIST COLOR:" at 6107.68,1841.64 h60
  text "X" at 6675.42,1682.44 h60
  text "GREEN" at 6802.46,1682.44 h60
  text "BLUE" at 7393.46,1682.44 h60
  text "OTHER" at 7931.46,1682.44 h60
  text "IMMERSION GOLD (ENIG)" at 7013.46,1493.92 h60
  text "SURFACE FINISH:" at 5952.46,1489.64 h60
  text "Pb-FREE HASL" at 8245.75,1489.64 h60
  text "X" at 8110,1480 h60
  text "OTHER" at 7013.46,1332.64 h60
  text "ARRAY/PANEL:" at 5952.46,1153.64 h60
  text "CUT AND TRIM PER MECH LAYER 1" at 7013.46,1149.35 h60
  text "X" at 6830,1140 h60
  text "N.C. ROUTE" at 7013.46,997.64 h60
  text "V. SCORE" at 7879.46,997.64 h60
  text "CERTIFICATION:" at 5952.46,860.64 h60
  text "MATERIALS AND WORKMANSHIP FOR ALL PCBS" at 6677.46,860.64 h60
  text "TO MEET OR EXCEED THE REQUIREMENTS OF:" at 6677.46,762.64 h60
  text "X" at 6303.96,626.13 h60
  text "ANSI IPC-A-600F CLASS ->" at 6442.96,626.13 h60
  text "X" at 8082.02,626.13 h60
  text "2" at 8200.96,626.14 h60
  text "1" at 7885.96,624.64 h60
  text "3" at 8554.96,624.64 h60
  text "X" at 6306.02,466.64 h60
  text "UL 94V-0" at 6442.96,466.64 h60
  text "X" at 7118.02,466.64 h60
  text "RoHS" at 7254.96,466.64 h60
  text "OTHER" at 7899.36,466.64 h60
  text "PER ORDER" at 8296.42,466.64 h60
  text "ADDITIONAL REQUIREMENTS:" at 5952.46,325.64 h60
  text "MICROSECTION:" at 6027.23,210.64 h60
  text "YES" at 6932.96,210.64 h60
  text "REQUIRED" at 7794.46,54.49 h60
  text "BARE BOARD ELEC. TEST:" at 6027.23,51.64 h60
  text "NONE" at 7332.96,51.64 h60
  text "X" at 7667.46,51.64 h60
  text "PER ORDER" at 8386.46,51.64 h60
  text "MANUFACTURER'S ID/LOGO:" at 6027.23,-105.36 h60
  text "RAIL" at 7492.96,-109.65 h60
  text "METAL" at 7984.77,-109.65 h60
  text "X" at 8353.49,-109.65 h60
  text "SILK" at 8496.46,-109.65 h60
  text ".Layer_Name" at 577,-858.49 h60
M11 Gerber Information:
  lines w10: -496.51,-1129 4403.49,-1129 ; -496.51,-929 4403.49,-929 ; 2203.49,-929 2203.49,-729 ; -496.51,-1329 -496.51,-729 4403.49,-729 4403.49,-1329 -496.51,-1329
  text "PCB VIEWED FROM TOP SIDE" at -246.51,-679 h60
  text "LAYER NAME =" at -246.51,-879 h60
  text "ARTWORK #    =" at 2253.49,-879 h60
  text ".PRJ_BasePN" at 3253.49,-879 h60
  text ".PCB_Rev" at 3753.49,-879 h60
  text "PLOT NAME =" at -246.51,-1079 h60
  text ".plot_File_Name" at 553.49,-1079 h60
  text "GENERATED    :" at -246.51,-1279 h60
  text ".Print_Date" at 622.99,-1279 h60
  text ".Print_Time" at 1303.49,-1279 h60
M12 Stackup:
  lines w11: -339,7105.5 5639,7105.5 ; -339,7309.2 5639,7309.2 ; -400,5166 ccw(c-334,5166) -334,5100 5634,5100 ccw(c5634,5166) 5700,5166 5700,7534 ccw(c5634,7534) 5634,7600 -334,7600 ccw(c-334,7534) -400,7534 -400,5166
  text "Layer Stack Up Detail for: 6573934 ADS8688 EVM.PcbDoc" at -339,7371.3 h111
  text "Layer" at -339,7233.2 h47
  text "Gerber" at 942.97,7233.2 h47
  text "Copper" at 1586.08,7233.2 h47
  text "Dielectric" at 2305.93,7233.2 h47
  text "Dielectric" at 3058.68,7233.2 h47
  text "Dielectric" at 4010.75,7233.2 h47
  text "Dielectric" at 4763.5,7233.2 h47
  text "Name" at -339,7139.2 h47
  text "Document" at 942.97,7139.2 h47
  text "Thickness" at 1586.08,7139.2 h47
  text "Height" at 2305.93,7139.2 h47
  text "Material" at 3058.68,7139.2 h47
  text "Constant" at 4010.75,7139.2 h47
  text "Type" at 4763.5,7139.2 h47
  text "Top Solder Mask" at -339,6987.5 h66
  text "(.GTS)" at 942.97,6987.5 h66
  text "0.4mil" at 2305.93,6987.5 h66
  text "Solder Resist" at 3058.68,6987.5 h66
  text "3.50" at 4010.75,6987.5 h66
  text "L1_Analog" at -339,6762.5 h66
  text "(.GTL)" at 942.97,6762.5 h66
  text "1.4mil" at 1586.08,6762.5 h66
  text "8mil" at 2305.93,6650 h66
  text "FR-4" at 3058.68,6650 h66
  text "4.80" at 4010.75,6650 h66
  text "Core" at 4763.5,6650 h66
  text "L2_GND" at -339,6537.5 h66
  text "(.GP1)" at 942.97,6537.5 h66
  text "1.4mil" at 1586.08,6537.5 h66
  text "10mil" at 2305.93,6425 h66
  text "FR-4" at 3058.68,6425 h66
  text "4.80" at 4010.75,6425 h66
  text "PrePreg" at 4763.5,6425 h66
  text "L3_AnalogPower" at -339,6312.5 h66
  text "(.G1)" at 942.97,6312.5 h66
  text "1.4mil" at 1586.08,6312.5 h66
  text "14mil" at 2305.93,6200 h66
  text "FR-4" at 3058.68,6200 h66
  text "4.80" at 4010.75,6200 h66
  text "Core" at 4763.5,6200 h66
  text "L4_DigPower" at -339,6087.5 h66
  text "(.G2)" at 942.97,6087.5 h66
  text "1.4mil" at 1586.08,6087.5 h66
  text "10mil" at 2305.93,5975 h66
  text "FR-4" at 3058.68,5975 h66
  text "4.80" at 4010.75,5975 h66
  text "PrePreg" at 4763.5,5975 h66
  text "L5_GND" at -339,5862.5 h66
  text "(.GP2)" at 942.97,5862.5 h66
  text "1.4mil" at 1586.08,5862.5 h66
  text "8mil" at 2305.93,5750 h66
  text "FR-4" at 3058.68,5750 h66
  text "4.80" at 4010.75,5750 h66
  text "Core" at 4763.5,5750 h66
  text "L6_Digital" at -339,5637.5 h66
  text "(.GBL)" at 942.97,5637.5 h66
  text "1.4mil" at 1586.08,5637.5 h66
  text "Bottom Solder Mask" at -339,5412.5 h66
  text "(.GBS)" at 942.97,5412.5 h66
  text "0.4mil" at 2305.93,5412.5 h66
  text "Solder Resist" at 3058.68,5412.5 h66
  text "3.50" at 4010.75,5412.5 h66
  text ".Layer_Name" at 577,-858.49 h60
M13 Component Bodies Top:
  text ".Layer_Name" at 577,-858.49 h60
M14 Component Bodies Bottom:
  text ".Layer_Name" at 577,-858.49 h60
M15 Courtyards Top:
  text ".Layer_Name" at 577,-858.49 h60
M16 Courtyards Bottom:
  text ".Layer_Name" at 577,-858.49 h60
Drill Drawing:
  lines w1: 0,0 0.03,0 ; 0,1700 0.03,1700 0,1700
  text ".legend" at 53.49,3821 h60
  text ".Layer_Name" at 527,-858.49 h60
M17 Fabrication:
  text "SEE NOTES" at 9631,1904.35 h120
  text "SEE NOTES" at 11231,1904.35 h120
  text "FABRICATION," at 11103.49,-279 h150
  text "1" at 13688,-1240.65 h80
  text "1" at 13981,-1295.65 h80

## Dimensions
0,0 to 0,2700 on M2 Board Dimensions
0,0 to 4100,0 on M2 Board Dimensions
